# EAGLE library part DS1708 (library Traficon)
CT: 05-03-2008 : changed name to DS1708 and set the SESA-suffix in the package name updated the symbol
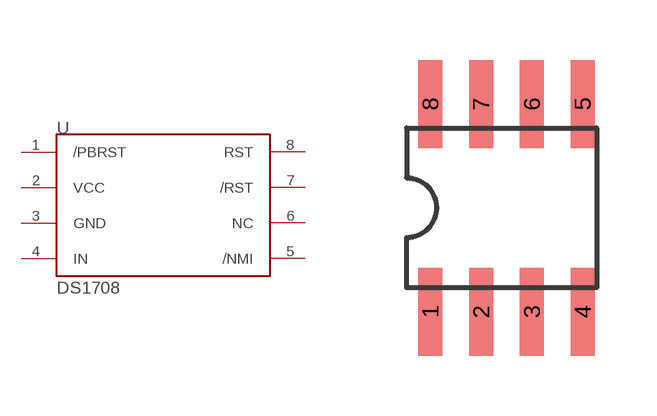
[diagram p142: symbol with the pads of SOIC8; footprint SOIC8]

Designator prefix U

## DS1708SESA  [SOIC8]
1  /PBRST  in
2  VCC  pwr
3  GND  pwr
4  IN  in
5  /NMI  out
6  NC  nc
7  /RST  out
8  RST  out

## Footprint SOIC8 (pad centres in mm)
Small Outline IC
smd 0.6 x 2.2: 1 -1.905,-2.6; 2 -0.635,-2.6; 3 0.635,-2.6; 4 1.905,-2.6; 5 1.905,2.6; 6 0.635,2.6; 7 -0.635,2.6; 8 -1.905,2.6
